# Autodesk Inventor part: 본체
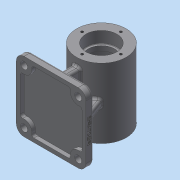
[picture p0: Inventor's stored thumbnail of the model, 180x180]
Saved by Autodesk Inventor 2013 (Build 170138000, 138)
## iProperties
Created: 2019-06
Part Number: 본체
Material: 일반
Document SubType Name: Modeling
Designer: Administrator
Density: 1 g/cm^3
Author: Administrator
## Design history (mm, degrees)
sketch "스케치1"
  geometry: C1 r 32 at (0, 0); 1 further point
  constraints: 1 centre point, 1 coincident
  dimensions: "d0" = 64 diameter of C1
extrude "돌출1" new body sketch "스케치1" distance "d1" = 45; taper "d2" = 0 deg
hole "구멍1" diameter "d5" = 34; stored, may be unused: countersink angle "d9" = 90 deg, drill point angle "d11" = 118 deg; dims "d3" = 10, "d4" = 10, "d6" = 6, "d7" = 40, "d8" = 15, "d10" = 8
sketch "스케치2"
  geometry: C1 r 17 at (0, 0) reference; C2 r 32 at (0, 0) reference; C3 r 25 at (0, 0)
  constraints: 1 centre point, 1 coincident
  dimensions: "d12" = 50 diameter of C3
extrude "돌출2" cut sketch "스케치2" distance "d13" = 24; taper "d14" = 0 deg
fillet "모깎기1" dims "d15" = 3
fillet "모깎기2" dims "d16" = 0.6
sketch "스케치3"
  geometry: C1 r 20 at (0, 0) reference; 1 further point
  constraints: 1 vertical alignment
  dimensions: "d17" = 25 distance of C1.centre point (0, 25)
hole "구멍2" sketch "스케치3" at (0, 25) diameter "d18" = 3.242; stored, may be unused: countersink angle "d22" = 90 deg, drill point angle "d24" = 118 deg; dims "d19" = 7, "d20" = 40, "d21" = 15, "d23" = 9
sketch "스케치4"
  geometry: L1 (-55, 45)-(-65, 45); L2 (-65, 45)-(-65, -45); L3 (-65, -45)-(-55, -45); L4 (-55, -45)-(-55, 45); 2 further points
  constraints: 8 end point, 2 parallel, 1 horizontal, 1 horizontal alignment, 1 midpoint, 1 perpendicular
  dimensions: "d28" = 10 distance of L3.end L2.end; "d29" = 90 distance of L2.end L1.end; "d30" = 65 distance from line of L2 point (0, 0)
extrude "돌출3" join sketch "스케치4" stored distance "d31" = 90; taper "d32" = 0 deg
fillet "모깎기3" dims "d33" = 10
fillet "모깎기4" dims "d34" = 3
sketch "스케치5"
  geometry: A1 r 7 centre (70, 7) between (70, 0) and (77, 7) reference; A2 r 7 centre (70, 77) between (77, 77) and (70, 84) reference; A3 r 7 centre (0, 77) between (0, 84) and (-7, 77) reference; A4 r 7 centre (0, 7) between (-7, 7) and (0, 0) reference; 4 further points
  constraints: 4 coincident
hole "구멍3" sketch "스케치5" at (0, 77), (0, 7), (70, 7), (70, 77) diameter "d35" = 9; stored, may be unused: countersink angle "d39" = 90 deg, drill point angle "d41" = 118 deg; dims "d36" = 7, "d37" = 40, "d38" = 15, "d40" = 9
sketch "스케치6"
  geometry: L1 (30, 77)-(40, 77); L2 (40, 77)-(40, 7); L3 (40, 7)-(30, 7); L4 (30, 7)-(30, 77); L5 (30, 77)-(40, 7); L6 (40, 77)-(30, 7); 1 further point
  constraints: 12 end point, 2 midpoint, 2 parallel, 1 horizontal, 1 perpendicular
  dimensions: "d42" = 10 distance of L2.end L3.end; "d43" = 70 distance of L1.end L2.end
extrude "돌출4" join sketch "스케치6" stored distance "d44" = 90; taper "d45" = 0 deg
sketch "스케치7"
  geometry: L1 (30.485, -42.595)-(35, -55); L2 (30.5, -55)-(39.5, -55) reference; L3 (45, -58)-(45, -65) reference; 1 further point
  constraints: 2 end point, 1 midpoint
  dimensions: "d46" = 110 deg angle of L1 L2; "d47" = 10 distance from line of L3 L1.end
feature "리브1" sketch "스케치7" dims "d48" = 1, "d49" = 10, "d50" = 0, "d51" = 0, "d52" = 1, "d53" = 1
fillet "모깎기5" dims "d54" = 3
fillet "모깎기6" dims "d55" = 3
node "작업 평면1"
sketch "스케치8"
  geometry: C1 r 5 at (-35, -45); 1 further point
  constraints: 1 centre point, 1 coincident
  dimensions: "d57" = 10 diameter of C1
extrude "돌출5" join sketch "스케치8" stored distance "d58" = 90; taper "d59" = 0 deg
fillet "모깎기7" dims "d60" = 2
hole "구멍4" diameter "d63" = 4.917; stored, may be unused: countersink angle "d67" = 90 deg, drill point angle "d69" = 118 deg; dims "d61" = 10, "d62" = 10, "d64" = 7, "d65" = 40, "d66" = 15, "d68" = 9
sketch "스케치9"
  geometry: L1 (80, -10)-(80, -80) reference; L2 (0, 0)-(70, 0) reference; L3 (-10, -80)-(-10, -10) reference; L4 (0, -90)-(70, -90) reference; L5 (-5, -5)-(8.66, -5); L6 (75, -5)-(75, -18.66); L7 (75, -85)-(61.34, -85); L8 (-5, -85)-(-5, -71.34); L9 (-5, -18.66)-(-5, -5); L10 (-5, -71.34)-(-5, -18.66); L11 (8.66, -85)-(-5, -85); L12 (61.34, -85)-(8.66, -85); L13 (75, -71.34)-(75, -85); L14 (75, -18.66)-(75, -71.34); L15 (61.34, -5)-(75, -5); L16 (8.66, -5)-(61.34, -5); A1 r 10 centre (70, -10) between (80, -10) and (70, 0) reference; A2 r 10 centre (0, -10) between (0, 0) and (-10, -10) reference; A3 r 10 centre (0, -80) between (-10, -80) and (0, -90) reference; A4 r 10 centre (70, -80) between (70, -90) and (80, -80) reference; A5 r 10 centre (0, -10) between (-5, -18.66) and (8.66, -5); A6 r 10 centre (0, -80) between (8.66, -85) and (-5, -71.34); A7 r 10 centre (70, -10) between (61.34, -5) and (75, -18.66); A8 r 10 centre (70, -80) between (75, -71.34) and (61.34, -85); 1 further point
  constraints: 29 end point, 18 parallel, 9 perpendicular, 8 point on circle, 4 centre point, 4 coincident, 3 horizontal
  dimensions: "d74" = 80 distance of L5.start L6.start; "d75" = 80 distance of L6.start L7.start; "d76" = 5 distance between parallel lines of L5 L2; "d77" = 5 distance between parallel lines of L1 L6; "d78" = 10 radius of A5; "d79" = 10 radius of A6; "d80" = 10 radius of A8; "d81" = 10 radius of A7
extrude "돌출6" cut sketch "스케치9" distance "d82" = 5; taper "d83" = 0 deg
fillet "모깎기8" dims "d84" = 3
sketch "스케치10"
  geometry: L1 (-35, -65)-(35, -65) reference; L2 (-45, -58)-(-45, -65) reference; 2 further points
  constraints: 1 other
  dimensions: "d85" = 4 distance from line of L1 point (0, -61); "d86" = 45 distance from line of point (0, -61) L2
feature "엠보싱1" sketch "스케치10" dims "d87" = 0.5, "d88" = 0
node "솔리드1"
pattern_circular "원형 패턴1" dims angle "d26" = 360 deg
mirror "대칭1"
mirror "대칭2"
